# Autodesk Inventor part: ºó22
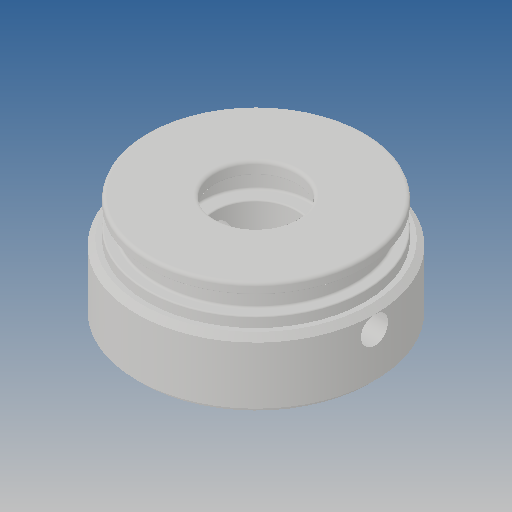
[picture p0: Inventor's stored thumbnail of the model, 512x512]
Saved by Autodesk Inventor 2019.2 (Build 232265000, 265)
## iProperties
Created: 2013-09
Part Number: ºó22
Material: Ogólny
Document SubType Name: Modeling
Designer: CADENGINEERING4
Density: 1 g/cm^3
Appearance: Domyślna
Author: CADENGINEERING4
Revision Number: ÈÎºÎ
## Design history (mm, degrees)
feature "µ¹½Ç1"
node "Bryła1"
